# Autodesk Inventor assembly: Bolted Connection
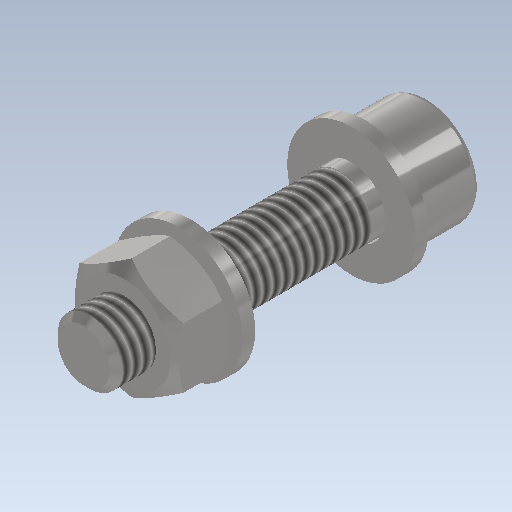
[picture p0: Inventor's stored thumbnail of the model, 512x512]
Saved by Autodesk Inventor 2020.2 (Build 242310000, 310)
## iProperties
ClientObjectVersion: 1
Created: 2020-01
Part Number: Bolted Connection
Document SubType Name: Assembly
Designer: thira
Mass: 29.971 g
Surface Area: 29.8218 cm^2
Volume: 3.8522 cm^3
Density: 7.78025 g/cm^3
Author: thira
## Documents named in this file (4)
- C:\Users\thira\OneDrive\เดสก์ท็อป\INV-01 Intro to Modeling_2020\Wheel Assem Final V1\Wheel Assy_Joint\Design Accelerator\Bolted Connection2.iam
- C:\Users\thira\OneDrive\เอกสาร\Inventor\Content Center Files\R2020\en-US\ISO 7089\ISO 7089 - 8 - 140 HV(1).ipt
- C:\Users\thira\OneDrive\เอกสาร\Inventor\Content Center Files\R2020\en-US\ISO 4762(2)\ISO 4762 - M8 x 35ISO.ipt
- C:\Users\thira\OneDrive\เอกสาร\Inventor\Content Center Files\R2020\en-US\ISO 4032(2)\ISO 4032 - M8 - ISO.ipt
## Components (4 placed, 3 different names)
1. ISO 7089 8:1
2. ISO 4762 M8 x 35:1
3. ISO 7089 8:2
4. ISO 4032 M8:1
